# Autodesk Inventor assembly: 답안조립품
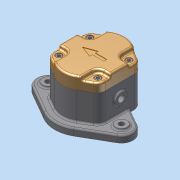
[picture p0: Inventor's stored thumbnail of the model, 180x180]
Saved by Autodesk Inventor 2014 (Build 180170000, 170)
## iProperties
Created: 2026-09
Part Number: 답안조립품
Document SubType Name: Assembly
Designer: dg
Author: dg
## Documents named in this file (11)
- C:\Users\dg\Desktop\660903V1010\답안조립품.iam
- C:\Users\dg\Desktop\660903V1010\가져온 구성요소\본체\본체.ipt
- C:\Users\dg\Desktop\660903V1010\가져온 구성요소\DU 부시\DU 부시.ipt
- C:\Users\dg\Desktop\660903V1010\가져온 구성요소\구동기어\구동기어.ipt
- C:\Users\dg\Desktop\660903V1010\가져온 구성요소\스퍼기어\스퍼기어.ipt
- C:\Users\dg\Desktop\660903V1010\가져온 구성요소\오일 실 16 30 7\오일 실 16 30 7.ipt
- C:\Users\dg\Desktop\660903V1010\가져온 구성요소\가이드 블록\가이드 블록.ipt
- C:\Users\dg\Desktop\660903V1010\가져온 구성요소\커버\커버.ipt
- C:\Users\dg\Desktop\660903V1010\가져온 구성요소\3자 실링\3자 실링.ipt
- C:\Users\dg\Desktop\660903V1010\가져온 구성요소\실링\실링.ipt
- C:\Users\dg\Desktop\660903V1010\가져온 구성요소\6각 구멍붙이 볼트 M6x16\6각 구멍붙이 볼트 M6x16.ipt
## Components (11 placed, 5 different names)
1. DU 부시:1
2. DU 부시:2
3. DU 부시:3
4. DU 부시:4
5. 구동기어:1
6. 가이드 블록:1
7. 3자 실링:1
8. 6각 구멍붙이 볼트 M6x16:1
9. 6각 구멍붙이 볼트 M6x16:2
10. 6각 구멍붙이 볼트 M6x16:3
11. 6각 구멍붙이 볼트 M6x16:4
